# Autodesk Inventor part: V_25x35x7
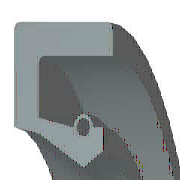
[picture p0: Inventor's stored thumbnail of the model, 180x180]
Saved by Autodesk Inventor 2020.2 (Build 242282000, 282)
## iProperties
Manager: www.cadconsulting.pl
Company: Fabian Stasiak CAD Consulting
Created: 2006-03
Part Number: V_25x35x7
Material: TS
Description: Pierścień uszczelniający 25x35x7-NBR
Vendor: Autodesk Inc.
Document SubType Name: Modeling
Standard: DIN 3760
Designer: F.Stasiak
Standards Organization: DIN
Language: pl-PL
Size Designation: A - 25 x 35 x 7 - NBR
Categories: <MemberInstance Version="R10.0.0"><Categories><Category DisplayName="Części wałów" InternalName="7f7aeb1f-a693-4053-b835-cee3144e0d98" Mnemonic="SHFT"><Category
Stock Number: PFP 1Z25357
Project: Przekładnia X51
Density: 1.06 g/cm^3
Appearance: Tworzywo sztuczne (czarne)
Author: F.Stasiak
Subject: Zbiór ćwiczeń. Autodesk Inventor 2020. Kurs podstawowy
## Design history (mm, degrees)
revolve "Bryła" stored, may be unused: angle "d17" = 90 deg
revolve "Sprężyna1" stored, may be unused: angle "d18" = 90 deg
node "Bryła1"
node "Korpusy bryłowe"
node "Korpusy powierzchniowe"
sketch "Szkic1"
  geometry: L1 (0, 17.5)-(7, 17.5); L2 (7, 17.5)-(7, 16.25); L3 (7, 16.25)-(1.75, 16.25); L4 (0, 17.5)-(0, 14.6); L5 (0, 14.6)-(1.75, 14.25); L6 (1.75, 14.25)-(4.9, 12.5); L7 (4.9, 12.5)-(0, 12.5); L8 (6.3, 13.375)-(6.3, 14.6); L9 (0, 0)-(9.586, 0) reference; L10 (4.9, 12.5)-(6.3, 13.375); L11 (0, 19.5)-(0, -1.5) reference; L12 (-0.959, 0)-(12.461, 0) reference; L13 (4.2, 14.6)-(1.75, 15.09); L14 (1.75, 15.09)-(1.75, 16.25); L15 (6.3, 14.6)-(5.6, 14.6); C1 r 0.455 at (4.9, 14.6); A1 r 0.7 centre (4.9, 14.6) between (5.6, 14.6) and (4.2, 14.6)
  constraints: 26 end point, 5 horizontal alignment, 4 perpendicular, 2 centre point, 2 collinear, 2 horizontal, 2 parallel, 2 point on circle, 2 point on line, 2 vertical alignment, 1 coincident
  dimensions: "d0" = 35 diameter of L1 L9 (= SD2); "d1" = 26.75 diameter of L8.start L9 (= ABDM); "d2" = 1.25 distance of L1.end L2.end (computed from SD); "d3" = 0.91 diameter of C1 (= SPDI); "d4" = 1.4 diameter of A1 (= SPDA); "d5" = 25 diameter of L6.end L9 (= NND); "d6" = 28.5 diameter of L5.end L9 (= TKDM); "d7" = 29.2 diameter of L4.end L9 (= HLDM); "d8" = 4.9 distance from line of C1.centre L4 (= SPDST); "d9" = 6.3 distance between parallel lines of L8 L4 (= SDI); "d10" = 7 distance between parallel lines of L2 L4 (= SWDT); "d12" = 1.75 distance between parallel lines of L14 L4 (= SD)
fillet "Zaokrąglenie1" dims "d11" = 0.3 (= RR)
other parameters: "SD2" = 35 [user parameter; used in 1 equation term], "SWDT" = 7 [user parameter; used in 1 equation term], "RR" = 0.3 [user parameter; used in 1 equation term], "SD" = 1.75 [user parameter; used in 2 equation terms], "NND" = 25 [user parameter; used in 1 equation term], "SPDA" = 1.4 [user parameter; used in 1 equation term], "SPDI" = 0.91 [user parameter; used in 1 equation term], "TKDM" = 28.5 [user parameter; used in 1 equation term], "HLDM" = 29.2 [user parameter; used in 1 equation term], "ABDM" = 26.75 [user parameter; used in 1 equation term], "SDI" = 6.3 [user parameter; used in 1 equation term], "SPDST" = 4.9 [user parameter; used in 1 equation term], "d13" = 0, "d14" = 0, "d15" = 0, "LAB" = 0.35 [user parameter]
